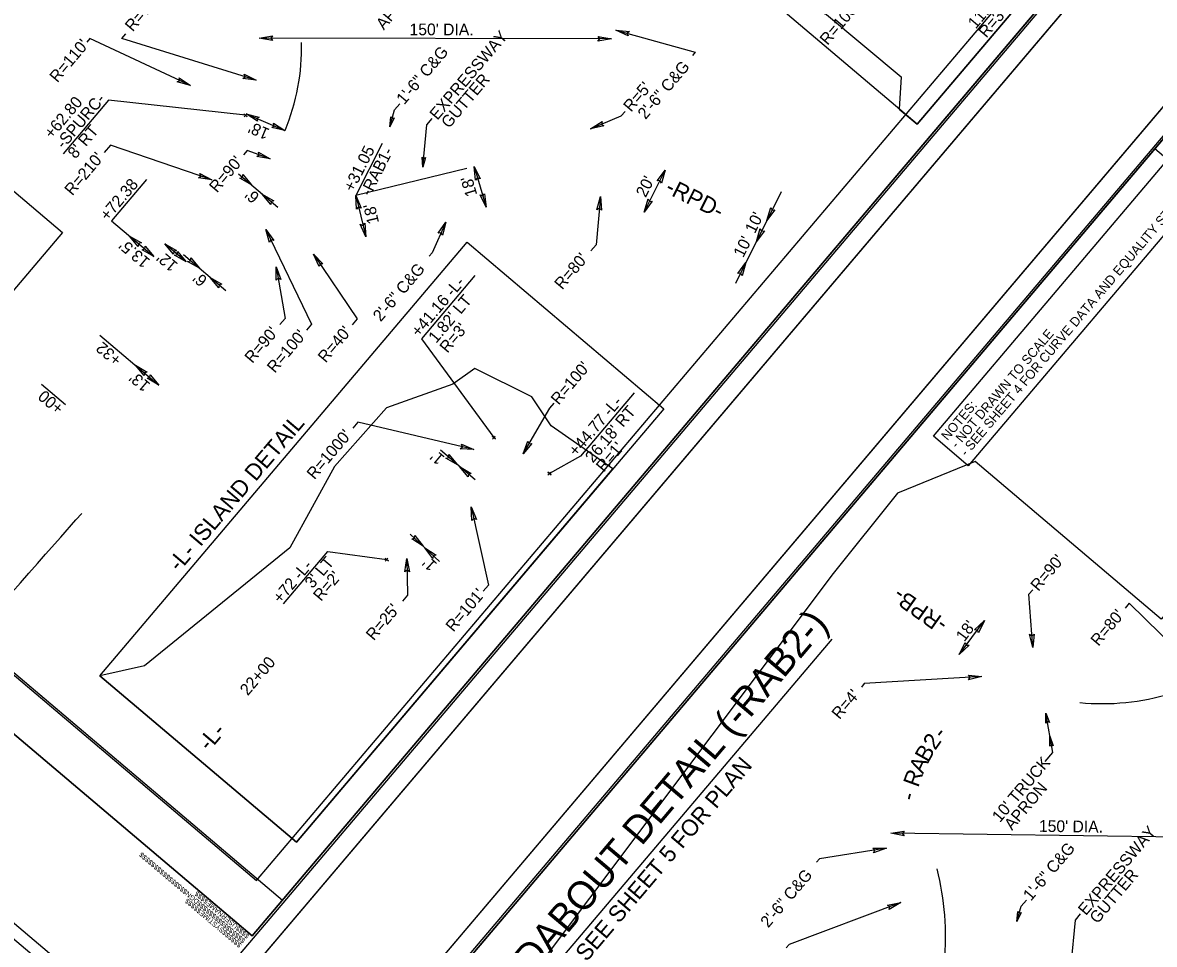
# Model space of a CAD drawing. Extents: x 1761753 to 1762923, y 422186 to 423380.
# Drawn here: x 1762047.4 to 1762529.4, y 422600.2 to 422992.9 of the extents above; entities that cross this region are included whole.
import ezdxf

# ---------------------------------------------------------------- set-up
doc = ezdxf.new("R2010")
doc.units = 0
for name, color, linetype in [('Default', 7, 'Continuous'), ('Prop Conc 2ft 6in Curb and Gutter', 7, 'Continuous'), ('Prop Conc 5in Monolithic Keyed In Island', 7, 'Continuous'), ('Prop Dimension Text', 7, 'Continuous'), ('Prop Grid Mask', 7, 'Continuous'), ('Prop Horizontal Alignment Station Label', 7, 'Continuous'), ('Prop Lane Lines', 7, 'Continuous'), ('Prop RDY Traffic Signal CELL', 7, 'Continuous'), ('Sheet Cutting Line CELL', 7, 'Continuous'), ('Sheet Data Field CELL', 7, 'Continuous'), ('Sheet North Arrow CELL', 7, 'Continuous'), ('Sheet Plan CELL', 7, 'Continuous'), ('Sheet Plot Border Outside CELL', 7, 'Continuous'), ('Sheet Symbology CELL', 7, 'Continuous')]:
    doc.layers.add(name, color=color, linetype=linetype)

# ---------------------------------------------------------------- blocks, each defined once
blk = doc.blocks.new('Terminator')
at = {"layer": 'Sheet Data Field CELL'}
blk.add_lwpolyline([(-9, 1.55), (0, 0), (-9.05, -1.6), (-7.9, 0)], close=True, dxfattribs=at)

msp = doc.modelspace()

# ---------------------------------------------------------------- linework, layer by layer
at = {"layer": 'Default'}
for p, q in [((1762142.15, 422953.55), (1762141.57, 422954.04)), ((1762142.99, 422952.85), (1762142.15, 422953.55)), ((1762247.89, 422816.26), (1762247.31, 422816.75)), ((1762248.72, 422815.56), (1762247.89, 422816.26)), ((1762271.59, 422800.92), (1762271.01, 422801.41)), ((1762272.42, 422800.22), (1762271.59, 422800.92)), ((1762202.29, 422764.25), (1762201.71, 422764.74)), ((1762203.12, 422763.55), (1762202.29, 422764.25))]:
    msp.add_line(p, q, dxfattribs=at)
at = {"layer": 'Prop Conc 2ft 6in Curb and Gutter'}
for points in [[(1762106.21, 422556.31), (1762536.95, 423064.78), (1762214.97, 423337.56), (1761784.22, 422829.09)], [(1762485.08, 422235.35), (1762915.83, 422743.82), (1762593.84, 423016.59), (1762163.09, 422508.12)]]:
    msp.add_lwpolyline(points, close=True, dxfattribs=at)
at = {"layer": 'Prop Conc 5in Monolithic Keyed In Island'}
msp.add_line((1762238.69, 422549.2), (1762392.09, 422730.28), dxfattribs=at)
for points in [[(1762337.14, 423026.87), (1762430.51, 423137.08), (1762521.72, 423059.81), (1762428.35, 422949.6)], [(1761852.77, 422866.3), (1761959.54, 422992.34), (1762064.33, 422903.57), (1761957.56, 422777.53)], [(1762080.21, 422714.69), (1762236.67, 422899.37), (1762320.43, 422828.42), (1762163.97, 422643.74)]]:
    msp.add_lwpolyline(points, close=True, dxfattribs=at)
at = {"layer": 'Prop Dimension Text'}
for p, q in [((1762108.95, 422547.17), (1762544.23, 423060.98)), ((1762588.9, 423023.14), (1762153.62, 422509.33))]:
    msp.add_line(p, q, dxfattribs=at)
at = {"layer": 'Prop Grid Mask'}
msp.add_line((1762145.13, 422603.81), (1762145.13, 422603.81), dxfattribs=at)
for points in [[(1762212.5, 423333.11), (1761824.66, 422875.29), (1762145.13, 422603.81), (1762532.96, 423061.62)], [(1762145.13, 422603.81), (1761824.66, 422875.28), (1762160.77, 423272.05), (1762206.57, 423233.25), (1762258.3, 423294.3), (1762532.96, 423061.62)], [(1762591.38, 423012.14), (1762203.53, 422554.33), (1762524, 422282.84), (1762911.83, 422740.65)], [(1762524, 422282.84), (1762203.54, 422554.31), (1762539.64, 422951.08), (1762585.45, 422912.29), (1762637.17, 422973.33), (1762911.83, 422740.65)]]:
    msp.add_lwpolyline(points, close=True, dxfattribs=at)
at = {"layer": 'Prop Horizontal Alignment Station Label'}
for points in [[(1762146.91, 422627.42), (1762512.32, 423058.75), (1762267, 423266.56), (1762215.18, 423205.39), (1762178.84, 423236.18), (1761865.25, 422866.02)], [(1762356.54, 423010.43), (1762389.75, 422996.33), (1762421.46, 422969.87), (1762420.74, 422956.05), (1762428.35, 422949.6), (1762521.72, 423059.81), (1762430.51, 423137.08), (1762337.14, 423026.87)], [(1762523.28, 422308.57), (1762722.11, 422543.28), (1762725.69, 422557.29), (1762715.43, 422577.81), (1762620.66, 422667), (1762762.51, 422846.79), (1762681.74, 422915.22), (1762532.27, 422738.78), (1762453.01, 422805.92), (1762420.01, 422792.47), (1762392.6, 422758.24), (1762237.08, 422551.03)], [(1762523.28, 422308.57), (1762722.11, 422543.28), (1762725.69, 422557.29), (1762715.43, 422577.81), (1762620.66, 422667), (1762762.51, 422846.79), (1762681.74, 422915.22), (1762532.27, 422738.78), (1762453.01, 422805.92), (1762420.01, 422792.47), (1762392.6, 422758.24), (1762237.08, 422551.03)], [(1762163.97, 422643.74), (1762298.73, 422802.8), (1762272.51, 422821.18), (1762264.19, 422833.54), (1762240.02, 422845.5), (1762230.56, 422838.87), (1762202.32, 422828.75), (1762180.25, 422803.85), (1762161.11, 422769.16), (1762099.24, 422718.84), (1762080.21, 422714.69)]]:
    msp.add_lwpolyline(points, close=True, dxfattribs=at)
at = {"layer": 'Prop Lane Lines'}
msp.add_line((1762236.58, 422930.74), (1762189.22, 422919.21), dxfattribs=at)
for centre, radius, start, end in [((1762076.16, 422981.94), 90, 337.1611, 1.6276), ((1762507.3, 422802.78), 100, 264.4409, 286.8732), ((1762320.42, 422603.39), 120, 354.8466, 13.9585)]:
    msp.add_arc(centre, radius, start, end, dxfattribs=at)
at = {"layer": 'Prop RDY Traffic Signal CELL'}
for points in [[(1761824.66, 422875.28), (1762145.13, 422603.81), (1762532.96, 423061.61), (1762277.04, 423278.41), (1762215.18, 423205.39), (1762150.64, 423260.08)], [(1762203.54, 422554.31), (1762524, 422282.84), (1762911.83, 422740.65), (1762655.91, 422957.45), (1762594.05, 422884.43), (1762529.51, 422939.11)]]:
    msp.add_lwpolyline(points, close=True, dxfattribs=at)
at = {"layer": 'Sheet Cutting Line CELL'}
msp.add_lwpolyline([(1762026.02, 422730.92), (1762039.5, 422746.35), (1762042.91, 422750.24), (1762046.43, 422754.25), (1762050.07, 422758.38), (1762053.68, 422762.47), (1762057.14, 422766.4), (1762063.59, 422773.73), (1762070.08, 422781.07), (1762072.51, 422783.8)], dxfattribs=at)
at = {"layer": 'Sheet Data Field CELL'}
for points in [[(1762141.75, 422971.02), (1762146.87, 422968.4), (1762141.13, 422969.13), (1762142.12, 422969.88)], [(1762218.96, 422935.5), (1762217.83, 422931.37), (1762217.49, 422935.67), (1762218.19, 422935.06)], [(1762153.1, 422915.48), (1762149.41, 422919.89), (1762154.41, 422916.97), (1762153.2, 422916.67)], [(1762118.93, 422892.69), (1762122.63, 422888.28), (1762117.63, 422891.2), (1762118.83, 422891.5)], [(1762237.1, 422799.41), (1762233.4, 422803.82), (1762238.4, 422800.9), (1762237.2, 422800.6)], [(1762214.45, 422774.45), (1762217.91, 422769.86), (1762213.07, 422773.03), (1762214.29, 422773.27)], [(1762483.19, 422694.48), (1762483.19, 422698.76), (1762484.65, 422694.71), (1762483.82, 422695.11)]]:
    msp.add_lwpolyline(points, close=True, dxfattribs=at)
at = {"layer": 'Sheet North Arrow CELL'}
for points in [[(1762108.95, 422547.17), (1762544.23, 423060.98), (1762210.03, 423344.1), (1761774.75, 422830.29)], [(1762487.82, 422226.21), (1762923.1, 422740.02), (1762588.9, 423023.14), (1762153.62, 422509.33)]]:
    msp.add_lwpolyline(points, close=True, dxfattribs=at)
at = {"layer": 'Sheet Plan CELL'}
for p, q in [((1762298.1, 422985.98), (1762148.1, 422986.26)), ((1762141.57, 422954.04), (1762142.99, 422952.85)), ((1762142.82, 422954.09), (1762141.67, 422952.74)), ((1762142.51, 422954), (1762159.1, 422947.01)), ((1762200.44, 422941.38), (1762189.22, 422919.21)), ((1762239.6, 422931.56), (1762244.81, 422914.33)), ((1762139.26, 422928.48), (1762156, 422914.3)), ((1762312.12, 422912.23), (1762321.03, 422930.13)), ((1762351.08, 422881.92), (1762370.49, 422920.94)), ((1762189.22, 422919.21), (1762193.48, 422901.72)), ((1762117.05, 422890.98), (1762107.89, 422898.74)), ((1762133.97, 422878.67), (1762115.91, 422893.97)), ((1762080.23, 422859.83), (1762105.38, 422838.52)), ((1762055.36, 422838.96), (1762065.62, 422830.27)), ((1762247.31, 422816.75), (1762248.72, 422815.56)), ((1762248.56, 422816.79), (1762247.41, 422815.44)), ((1762240.13, 422798.12), (1762225.26, 422810.72)), ((1762271.01, 422801.41), (1762272.42, 422800.22)), ((1762272.26, 422801.45), (1762271.11, 422800.1)), ((1762224.9, 422763.28), (1762212.41, 422775.04)), ((1762201.71, 422764.74), (1762203.12, 422763.55)), ((1762202.95, 422764.79), (1762201.81, 422763.43)), ((1762446.27, 422723.68), (1762456.98, 422738.14)), ((1762567.08, 422645.49), (1762417.09, 422647.54))]:
    msp.add_line(p, q, dxfattribs=at)
for points in [[(1762300.01, 422989.71), (1762333.79, 422980.33), (1762332.62, 422978.95)], [(1762118.79, 422966.14), (1762075.97, 422986.12), (1762074.73, 422984.66)], [(1762146.87, 422968.4), (1762089.61, 422986.21), (1762091.27, 422988.18)], [(1762142.28, 422953.45), (1762083.98, 422959.94), (1762064.61, 422937.07)], [(1762203.73, 422948.57), (1762205.77, 422955.75), (1762207.99, 422958.37)], [(1762289.27, 422947.65), (1762302.26, 422953.16), (1762303.92, 422955.13)], [(1762217.83, 422931.37), (1762219.57, 422949.45), (1762221.79, 422952.06)], [(1762127.92, 422925.92), (1762084.79, 422940.75), (1762082.14, 422937.6)], [(1762152.85, 422934.85), (1762142.98, 422938.41), (1762141.47, 422936.63)], [(1762100.15, 422926.12), (1762085.23, 422908.51), (1762103.22, 422893.27)], [(1762293.46, 422918.78), (1762291.56, 422898.29), (1762289.36, 422895.69)], [(1762227.59, 422907.96), (1762221.71, 422894.88), (1762220.47, 422893.42)], [(1762150.95, 422904.84), (1762170.42, 422864.43), (1762168.22, 422861.84)], [(1762171.25, 422894.32), (1762189.84, 422866.72), (1762187.64, 422864.12)], [(1762155.31, 422888.9), (1762159.13, 422866.88), (1762156.93, 422864.28)], [(1762240, 422885.17), (1762217.21, 422858.26), (1762248.01, 422816.15)], [(1762307.8, 422835.16), (1762285.01, 422808.25), (1762271.71, 422800.82)], [(1762260.59, 422809.22), (1762271.86, 422828.7), (1762273.68, 422830.85)], [(1762239.55, 422811.01), (1762190.18, 422822.7), (1762187.97, 422820.1)], [(1762238.39, 422786.57), (1762245.77, 422753.24), (1762243.57, 422750.64)], [(1762158.43, 422745.29), (1762177.32, 422767.58), (1762202.41, 422764.15)], [(1762210.96, 422764.66), (1762211.32, 422748.97), (1762209.12, 422746.38)], [(1762477.59, 422726.72), (1762475.91, 422749.36), (1762477.57, 422751.33)], [(1762538.85, 422725.82), (1762518.65, 422745.52), (1762516.87, 422743.41)], [(1762455.89, 422714.32), (1762405.81, 422711.32), (1762404.57, 422709.86)], [(1762482.85, 422678.19), (1762486.05, 422681.97), (1762483.19, 422698.76)], [(1762415.27, 422641.15), (1762386.76, 422636.67), (1762385.52, 422635.21)], [(1762421.36, 422618.07), (1762373.76, 422600.17), (1762372.52, 422598.71)], [(1762470.84, 422610), (1762472.69, 422616.49), (1762474.9, 422619.1)], [(1762493.92, 422591.55), (1762495.75, 422610.59), (1762497.97, 422613.2)]]:
    msp.add_lwpolyline(points, dxfattribs=at)
msp.add_lwpolyline([(1762435.24, 422816.71), (1762540.64, 422941.12), (1762555.5, 422928.53), (1762450.1, 422804.12)], close=True, dxfattribs=at)
at = {"layer": 'Sheet Symbology CELL'}
for points in [[(1762158.05, 422619.07), (1762520.03, 423046.36), (1762264.12, 423263.16), (1762215.18, 423205.39), (1762150.64, 423260.08), (1761837.59, 422890.55)], [(1762536.93, 422298.1), (1762898.91, 422725.39), (1762642.99, 422942.19), (1762594.05, 422884.43), (1762529.51, 422939.11), (1762216.46, 422569.59)]]:
    msp.add_lwpolyline(points, close=True, dxfattribs=at)

# ---------------------------------------------------------------- block references
at = {"layer": 'Default'}
for p, xscale, yscale, rotation in [((1762300.01, 422989.71), 0.6300000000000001, 0.6299999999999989, 164.47050309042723), ((1762148.1, 422986.26), 0.6300000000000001, 0.6299999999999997, 179.89479358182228), ((1762298.1, 422985.98), 0.6300000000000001, 0.6299999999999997, -0.10520641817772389), ((1762118.79, 422966.14), 0.6300000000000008, 0.6299999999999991, -25.006555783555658), ((1762142.51, 422954), 0.63, 0.6299999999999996, 157.1611204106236), ((1762159.1, 422947.01), 0.63, 0.6299999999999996, -22.838879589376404), ((1762289.27, 422947.65), 0.6300000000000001, 0.6299999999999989, -157.04275375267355), ((1762152.85, 422934.85), 0.6300000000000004, 0.6299999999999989, -19.891890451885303), ((1762239.6, 422931.56), 0.6300000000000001, 0.6299999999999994, 106.83156475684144), ((1762321.03, 422930.13), 0.6300000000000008, 0.6299999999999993, 63.548333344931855), ((1762127.92, 422925.92), 0.6300000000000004, 0.6299999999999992, -18.974325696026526), ((1762144.83, 422923.77), 0.6300000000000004, 0.6299999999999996, -40.26989656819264), ((1762189.22, 422919.21), 0.6300000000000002, 0.6299999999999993, 103.68213112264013), ((1762244.81, 422914.33), 0.6300000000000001, 0.6299999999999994, -73.16843524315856), ((1762293.46, 422918.78), 0.63, 0.6299999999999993, 84.71528857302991), ((1762312.12, 422912.23), 0.6300000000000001, 0.6299999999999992, -116.45166666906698), ((1762364.34, 422908.58), 0.6300000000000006, 0.6299999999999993, -116.4516666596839), ((1762193.48, 422901.72), 0.6300000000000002, 0.6299999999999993, -76.31786887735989), ((1762227.59, 422907.96), 0.63, 0.6299999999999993, 65.77365248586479), ((1762092.94, 422901.97), 0.6300000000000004, 0.6299999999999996, 139.73010343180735), ((1762150.95, 422904.84), 0.63, 0.6299999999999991, 115.73179052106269), ((1762359.89, 422899.63), 0.6300000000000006, 0.6299999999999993, -116.4516666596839), ((1762103.22, 422893.27), 0.6300000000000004, 0.6299999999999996, -40.26989656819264), ((1762107.89, 422898.74), 0.6300000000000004, 0.6299999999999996, 139.73010343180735), ((1762117.05, 422890.98), 0.6300000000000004, 0.6299999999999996, -40.26989656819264), ((1762171.25, 422894.32), 0.6300000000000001, 0.6299999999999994, 123.95908035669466), ((1762155.31, 422888.9), 0.6300000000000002, 0.6299999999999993, 99.84022934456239), ((1762355.43, 422890.67), 0.6300000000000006, 0.6299999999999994, 63.54833334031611), ((1762127.21, 422884.4), 0.6300000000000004, 0.6299999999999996, 139.73010343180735), ((1762095.46, 422846.93), 0.6300000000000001, 0.6299999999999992, 139.73010343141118), ((1762105.38, 422838.52), 0.6300000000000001, 0.6299999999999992, -40.269896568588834), ((1762239.55, 422811.01), 0.63, 0.6299999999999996, -13.323349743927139), ((1762260.59, 422809.22), 0.63, 0.6299999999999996, -120.0483558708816), ((1762232.64, 422804.47), 0.630000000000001, 0.629999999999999, -40.26989657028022), ((1762238.39, 422786.57), 0.6300000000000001, 0.6299999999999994, 102.48274759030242), ((1762218.64, 422769.17), 0.6300000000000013, 0.6299999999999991, 136.74488336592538), ((1762210.96, 422764.66), 0.6299999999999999, 0.6299999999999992, 91.3198900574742), ((1762456.98, 422738.14), 0.63, 0.6299999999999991, 53.490833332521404), ((1762446.27, 422723.68), 0.6299999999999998, 0.6299999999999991, -126.50916666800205), ((1762477.59, 422726.72), 0.6300000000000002, 0.6299999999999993, -85.74258899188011), ((1762455.89, 422714.32), 0.6300000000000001, 0.6299999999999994, 3.4253964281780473), ((1762417.09, 422647.54), 0.6300000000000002, 0.6299999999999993, 179.22005220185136), ((1762415.27, 422641.15), 0.63, 0.6299999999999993, 8.927593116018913), ((1762421.36, 422618.07), 0.63, 0.6299999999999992, 20.607955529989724)]:
    msp.add_blockref('Terminator', p, dxfattribs=dict(at, xscale=xscale, yscale=yscale, rotation=rotation))
at = {"layer": 'Sheet Plan CELL'}
for p, xscale, yscale, rotation in [((1762203.73, 422948.57), 0.4687697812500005, 0.46876978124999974, -105.90915921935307), ((1762484.87, 422688.91), 0.46876978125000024, 0.46876978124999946, 99.6589603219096), ((1762470.84, 422610), 0.4687697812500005, 0.46876978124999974, -105.90915921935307)]:
    msp.add_blockref('Terminator', p, dxfattribs=dict(at, xscale=xscale, yscale=yscale, rotation=rotation))

# ---------------------------------------------------------------- texts
at = {"layer": 'Prop Dimension Text'}
for s, height, rotation, p in [("11.72' RT", 5, 49.7301, (1762453.28, 422989.96)), ('APRON', 5, 49.7301, (1762201.2, 422989.53)), ("R=72'", 5, 49.7301, (1762094.28, 422988.75)), ("R=100'", 5, 49.7301, (1762390.19, 422982.99)), ("R=3'", 5, 49.7301, (1762457.8, 422986.13)), ("150' DIA.", 5, 359.8948, (1762212.14, 422987.55)), ('EXPRESSWAY', 5, 49.7301, (1762224.02, 422951.1)), ("R=110'", 5, 49.7301, (1762062.16, 422967.08)), ('1\'-6" C&G', 5, 49.7301, (1762209.87, 422957.67)), ('2\'-6" C&G', 5, 49.7301, (1762312.64, 422951.37)), ('GUTTER', 5, 49.7301, (1762228.95, 422947.58)), ("R=5'", 5, 49.7301, (1762306.53, 422954.53)), ('+62.80', 5, 49.7301, (1762059.87, 422943.07)), ('-SPURC-', 5, 49.7301, (1762064.87, 422938.83)), ("8' RT", 5, 49.7301, (1762069.87, 422934.6)), ("18'", 5, 157.1611, (1762152.93, 422947.44)), ('+31.05', 5, 63.1463, (1762188.19, 422920.46)), ("R=210'", 5, 49.7301, (1762068.52, 422918.91)), ("R=90'", 5, 49.7301, (1762130.14, 422920.14)), ('-RAB1-', 5, 63.1463, (1762195.45, 422918.67)), ('+72.38', 5, 49.7301, (1762083.6, 422908.12)), ("18'", 5, 106.8316, (1762241.05, 422919.62)), ("20'", 5, 63.5483, (1762312.74, 422918.13)), ("6'", 5, 139.7301, (1762148.61, 422919.31)), ("18'", 5, 103.6821, (1762199.23, 422907.76)), ("10'", 5, 63.5483, (1762359.19, 422902.76)), ("10'", 5, 63.5483, (1762354.25, 422892.48)), ("13.5'", 5, 139.7301, (1762102, 422891.71)), ("12'", 5, 139.7301, (1762113.83, 422890.1)), ("R=80'", 5, 49.7301, (1762277.17, 422878.83)), ('2\'-6" C&G', 5, 49.7301, (1762199.87, 422865.2)), ("6'", 5, 139.7301, (1762126.41, 422883.83)), ('+41.16 -L-', 5, 49.7301, (1762216.13, 422858.68)), ("1.82' LT", 5, 49.7301, (1762223.5, 422856.06)), ("R=90'", 5, 49.7301, (1762145.23, 422847.45)), ("R=40'", 5, 49.7301, (1762176.43, 422847.69)), ("R=3'", 5, 49.7301, (1762228.28, 422851.84)), ("R=100'", 5, 49.7301, (1762154.77, 422843.31)), ('+32', 5, 139.7301, (1762089.99, 422849.96)), ("R=100'", 5, 49.7301, (1762275.65, 422829.72)), ("13'", 5, 139.7301, (1762102.1, 422838.93)), ('+00', 5, 139.7301, (1762065.33, 422829.38)), ('+44.77 -L-', 5, 49.7301, (1762283.15, 422807.76)), ("26.18' RT", 5, 49.7301, (1762290.25, 422805.04)), ('-L- ISLAND DETAIL', 7, 49.7301, (1762113.99, 422758.62)), ("R=1000'", 5, 49.7301, (1762171.68, 422797.93)), ("1'", 5, 139.7301, (1762227.46, 422807.8)), ("R=1'", 5, 49.7301, (1762294.89, 422801.12)), ("R=90'", 5, 49.7301, (1762479.95, 422750.36)), ('+72 -L-', 5, 49.7301, (1762157.22, 422745.1)), ("3' LT", 5, 49.7301, (1762170.85, 422751.52)), ("1'", 5, 136.7449, (1762224.18, 422762.33)), ("R=2'", 5, 49.7301, (1762174.44, 422746.09)), ("R=101'", 5, 49.7301, (1762230.86, 422733.01)), ("R=25'", 5, 49.7301, (1762196.91, 422729.33)), ("R=80'", 5, 49.7301, (1762505.56, 422726.96)), ('ROUNDABOUT DETAIL (-RAB2-)', 12, 49.7301, (1762234.28, 422551.33)), ("18'", 5, 53.4908, (1762448.43, 422728.83)), ("R=4'", 5, 49.7301, (1762395.26, 422695.76)), ('SEE SHEET 5 FOR PLAN', 7, 49.7301, (1762287.54, 422592.54)), ("10' TRUCK", 5, 49.7301, (1762463.57, 422651.84)), ('APRON', 5, 49.7301, (1762468.74, 422648.52)), ("150' DIA.", 5, 359.2201, (1762480.17, 422648.19)), ('EXPRESSWAY', 5, 49.7301, (1762500.2, 422612.24)), ('1\'-6" C&G', 5, 49.7301, (1762476.78, 422618.41)), ('2\'-6" C&G', 5, 49.7301, (1762364.92, 422606.99)), ('GUTTER', 5, 49.7301, (1762505.12, 422608.72))]:
    msp.add_text(s, height=height, rotation=rotation, dxfattribs=at).set_placement(p)
at = {"layer": 'Prop Grid Mask'}
for s, p in [('$$$$$$$$$$$$$$$$DGN$$$$$$$$$$$$$$$$', (1762142.43, 422602.09)), ('$$$$USERNAME$$$$', (1762144.12, 422604.09)), ('$$$$$$SYSTIME$$$$$', (1762140.87, 422600.23))]:
    msp.add_text(s, height=2.1, rotation=139.7301, dxfattribs=at).set_placement(p)
at = {"layer": 'Sheet Plan CELL'}
for s, p in [('- SEE SHEET 4 FOR CURVE DATA AND EQUALITY STATIONS', (1762449.28, 422807.83)), ('- NOT DRAWN TO SCALE', (1762445.28, 422811.22)), ('NOTES:', (1762441.28, 422814.61))]:
    msp.add_text(s, height=4, rotation=49.7301, dxfattribs=at).set_placement(p)
at = {"layer": 'Sheet Plot Border Outside CELL'}
for s, height, rotation, p in [('-RPD-', 7, 333.5385, (1762320.57, 422920.72)), ('-RPB-', 7, 144.5689, (1762441.84, 422737.86)), ('22+00', 5, 49.7301, (1762143.25, 422705.88)), ('-L-', 7, 49.7301, (1762126.76, 422682.21)), ('2', 7, 55.2723, (1762436.03, 422682.66)), ('-', 7, 50.4724, (1762439.25, 422687.37)), ('B', 7, 60.4097, (1762433.04, 422677.35)), ('A', 7, 64.8728, (1762430.83, 422672.53)), ('R', 7, 70.0102, (1762428.77, 422666.78)), ('-', 7, 75.0614, (1762427.25, 422660.98))]:
    msp.add_text(s, height=height, rotation=rotation, dxfattribs=at).set_placement(p)

doc.saveas('drawing.dxf')
